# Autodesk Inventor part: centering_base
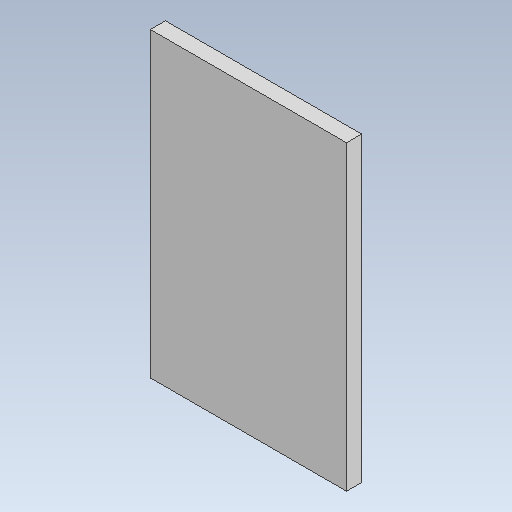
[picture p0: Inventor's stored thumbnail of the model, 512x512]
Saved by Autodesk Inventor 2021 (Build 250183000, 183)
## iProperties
Created: 2026-10
Part Number: centering_base
Material: Generic
Document SubType Name: Modeling
Designer: alolo
Density: 1 g/cm^3
Appearance: Default
Author: alolo
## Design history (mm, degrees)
sketch "Sketch1"
  geometry: L1 (0, 0)-(65, 0); L2 (65, 0)-(65, 100); L3 (65, 100)-(0, 100); L4 (0, 100)-(0, 0)
  constraints: 8 end point, 2 parallel, 1 horizontal, 1 perpendicular
  dimensions: "d0" = 65 distance of L3.end L2.end (= slide_width); "d3" = 100 distance of L1.end L2.end
extrude "Extrusion1" new body sketch "Sketch1" distance "d1" = 5 (= wood_thickness); taper "d2" = 0 deg
body "Solid1"
other parameters: "slide_length" = 195 [user parameter], "slide_angle" = 7 deg [user parameter], "slide_width" = 65 [user parameter; used in 1 equation term], "wood_thickness" = 5 [user parameter; used in 1 equation term], "aclyric_thickness" = 6 [user parameter]
